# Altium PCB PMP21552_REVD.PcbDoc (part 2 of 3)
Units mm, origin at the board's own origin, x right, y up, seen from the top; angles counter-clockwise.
Board outline 45.05 x 86.02 mm, 4 copper layers (Top Layer, Signal Layer 1, Signal Layer 2, Bottom Layer), stack 1.006 mm thick; 146 components, 80 nets, 395 pads, 82 vias.
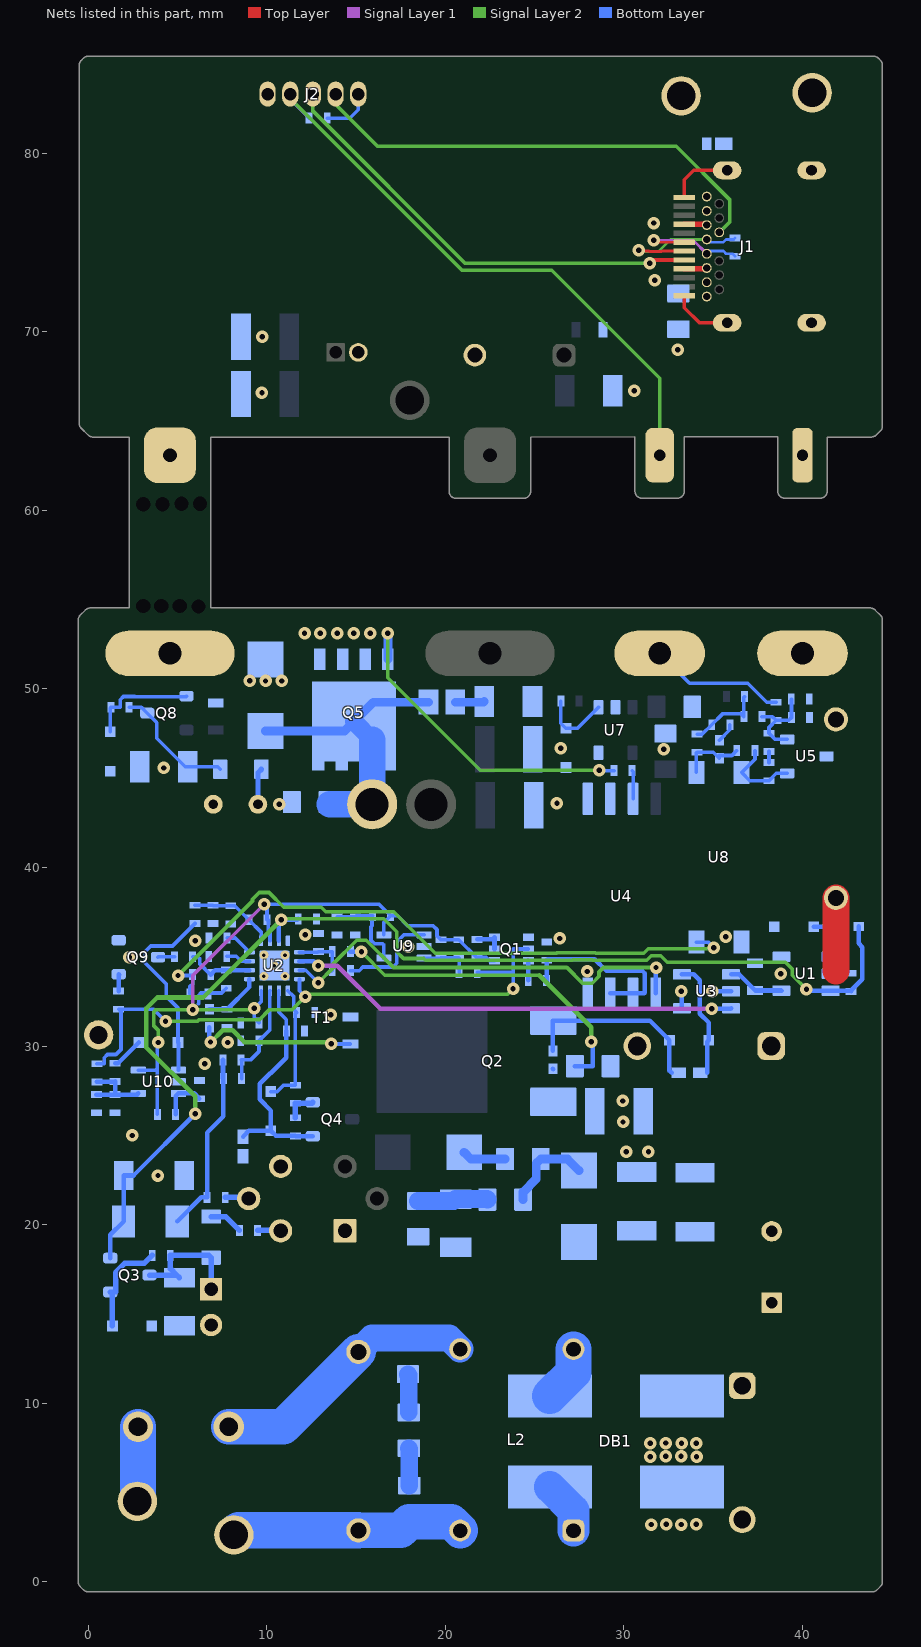
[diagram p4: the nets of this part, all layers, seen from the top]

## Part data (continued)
C33: library part CMP-0008251-2, "CAP, CERM, 1000 pF, 250 V, +/- 10%, X7R, 0805", Cap_Case=0805, Manufacturer=MuRata, Supplier Part Number 1=490-3525-1-ND, TempCo=X7R, Tolerance_%=10%, Value1=Unknown, Value2=250V, ValueDisplayed=1000pF
C34: library part CMP-0008252-2, "CAP, CERM, 1500 pF, 250 V, +/- 10%, X7R, 0805", Cap_Case=0805, Manufacturer=MuRata, Supplier Part Number 1=490-3527-1-ND, TempCo=X7R, Tolerance_%=10%, Value1=Unknown, Value2=250V, ValueDisplayed=1500pF
C36: library part CMP-0008995-2, "CAP, CERM, 0.22 uF, 50 V, +/- 10%, X7R, 1206", Cap_Case=1206, Manufacturer=MuRata, Supplier Part Number 1=GRM31MR71H224KA01L-ND, TempCo=X7R, Tolerance_%=10%, Value1=Unknown, Value2=50V, ValueDisplayed=0.22uF
C37: library part CMP-0081668-2, "CAP, Aluminum Polymer, 680 µF, 25 V,+/- 20%, 0.29256 ohm, TH", Cap_Case=10x12mm, Manufacturer="Illinois Capacitor", Supplier Part Number 1=1572-1754-ND, Tolerance_%=20%, Value1="0.29256 ohm", Value2=25V, ValueDisplayed=680µF
C43: library part CMP-0006674-2, "CAP, CERM, 0.01 uF, 50 V, +/- 10%, X7R, 0402", Cap_Case=0402, Manufacturer=MuRata, Supplier Part Number 1=490-4516-1-ND, TempCo=X7R, Tolerance_%=10%, Value1=Unknown, Value2=50V, ValueDisplayed=0.01uF
C44: library part CMP-0008487-2, "CAP, CERM, 0.1 uF, 100 V, +/- 5%, X7R, 1206", Cap_Case=1206, Manufacturer=AVX, Supplier Part Number 1=478-3785-1-ND, TempCo=X7R, Tolerance_%=5%, Value1="0.037 ohm", Value2=100V, ValueDisplayed=0.1uF
D1 D13: library part CMP-0005829-1, "Diode, Zener, 10 V, 200 mW, SOD-323", Manufacturer="Diodes Inc.", Power_W=200mW, Supplier Part Number 1=MMSZ5240BS-FDICT-ND, Value1=0.2W
D2: "Diode, Zener, 9.1 V, 200 mW, SOD-323", Manufacturer="Diodes Inc.", Power_W=0.2, Supplier Part Number 1=BZT52C9V1S-FDICT-ND, Value1=0.2W
D3: library part CMP-0029199-1, "Diode, Superfast Rectifier, 200 V, 1 A, 3.5x1.6mm", Manufacturer="Comchip Technology", Supplier Part Number 1=641-1438-1-ND, Value1=1A, Value2=0.95V
D4 D21: library part CMP-0077868-1, "Diode, Standard Recovery Rectifier, 800 V, .2 A, 2x1.4mm", Manufacturer=Rohm, Supplier Part Number 1=RFU02VSM8SCT-ND, Value1=.2A, Value2=2.2V
D5: library part CMP-0005833-2, "Diode, Zener, 15 V, 200 mW, SOD-323", Manufacturer="Diodes Inc.", Power_W=200mW, Supplier Part Number 1=MMSZ5245BS-FDICT-ND, Value1=0.2W
D6: library part CMP-0005822-3, "Diode, TVS, Bi, 18 V, SOD-323", Manufacturer=Bourns, Value1=350W
D7: library part CMP-0005884-3, "Diode, Zener, 22 V, 300 mW, SOD-523", Manufacturer="Diodes Inc.", Power_W=300mW, Supplier Part Number 1=BZT52C22T-7DICT-ND, Value1=0.3W
D8: library part CMP-0028829-1, "Diode, Schottky, 30 V, 2 A, 2-XFDFN", Manufacturer="ON Semiconductor", Supplier Part Number 1=NSR20F30NXT5GOSCT-ND, Value1=2A, Value2=0.48V
D10: library part CMP-0077082-1, "Diode, Standard Recovery Rectifier, 1000 V, 1 A, AEC-Q101, SMA", Manufacturer="ON Semiconductor", Supplier Part Number 1=MRA4007T3GOSCT-ND, Value1=1A, Value2=1.1V
D11: library part CMP-0084982-1, "Diode, TVS, Uni, 150 V, 243 Vc, 400 W, 1.6 A, SMA", Manufacturer=Littelfuse, Value1=243V
D12 D100: library part CMP-0029006-2, "Diode, Ultrafast, 100 V, 0.25 A, SOD-323", Manufacturer=Nexperia, Value1=0.25A, Value2=1.4V
D14: library part CMP-0005466-2, "Diode, TVS, Bi, 100 V, SMA", Manufacturer=Littelfuse, Power_W=3.3W, Supplier Part Number 1=SMAJ100CALFCT-ND
DB1: "Diode, P-N-Bridge, 600 V, 4 A, Z4-D", Manufacturer="Comchip Technology", Supplier Part Number 1=641-1502-1-ND, Value1=4A, Value2=0.95V
F1: library part CMP-0003561-2, "Fuse, 3.15 A, 250VAC/VDC, TH", Irating_A=3.15A, Manufacturer=Littelfuse, Supplier Part Number 1=F5504CT-ND
J1: library part CMP-0054818-1, "Connector, Receptacle, USB Type C, R/A", Color=Black, Current_A=3A, Manufacturer="Wurth Elektronik", Voltage_V=5V
J2: library part CMP-0054560-1, "Header, 50mil, 5x1, Gold, TH", Manufacturer="Sullins Connector Solutions", Supplier Part Number 1=S9014E-05-ND
J3: library part CMP-0054555-1, "Header, 50mil, 2x1, Gold, TH", Manufacturer="Sullins Connector Solutions", Supplier Part Number 1=S9014E-02-ND
L1: library part CMP-0087546-1, "WE-FI Leaded Toroidal Line Choke", Manufacturer=Wurth
L2: library part CMP-0086351-1, "Coupled inductor, 1.3 mH, 0.035 ohm, TH", Manufacturer="Renco Electronics", ValueDisplayed=1.3mH
LOGO1: library part IEC_HighVoltage, "IEC 61010-1 High Voltage Warning"
LOGO2: library part CMP-0074837-1, "IEC 61010-1 Hot Surface Warning"
Logo3: library part CMP-0074839-1
Logo4: library part CMP-0074769-1
Q1: library part CMP-0000173-4, "MOSFET, 2-CH, N/P-CH, 20 V, 0.7 A, SOT-363", Alternate Manufacturer=None, Manufacturer=Vishay-Siliconix, Value1=0.3, Value2="1.2 nC"
Q2: library part CMP-0079238-2, "MOSFET, N-CH, 600 V, 12 A, DPAK", Alternate Manufacturer=None, Manufacturer="Infineon Technologies", Supplier Part Number 1=IPD60R280P7SAUMA1CT-ND, Value1="? ohm", Value2="18 nC"
Q3 Q8: "MOSFET, N-CH, 100 V, 0.17 A, SOT-23", Alternate Manufacturer=None, Manufacturer="Fairchild Semiconductor", Supplier Part Number 1=BSS123NCT-ND, Value1="10 ohm", Value2="1.8 nC"
Q4: library part CMP-0067574-1, "MOSFET, N-CH, 600 V, 0.021 A, AEC-Q101, SOT-23", Alternate Manufacturer=None, Manufacturer="Infineon Technologies", Supplier Part Number 1=BSS126H6327XTSA2CT-ND, Value1="? ohm", Value2="1.4 nC"
Q5: library part CMP-0001046-2, "MOSFET, N-CH, 150 V, 87 A, PG-TDSON-8", Alternate Manufacturer=None, Manufacturer="Infineon Technologies", Supplier Part Number 1=BSC093N15NS5ATMA1CT-ND, Value2="33 nC"
Q9: library part CMP-0000281-1, "MOSFET, N-CH, 25 V, 0.22 A, SOT-23", Alternate Manufacturer=None, Manufacturer="Fairchild Semiconductor", Supplier Part Number 1=FDV301NCT-ND, Value2="0.49 nC"
R1: library part CMP-0026555-2, "RES, 7.50 k, 1%, 0.063 W, AEC-Q200 Grade 0, 0402", Manufacturer=Vishay-Dale, Power_W=63mW, Supplier Part Number 1=541-7.50KLCT-ND, TempCo="100 ppm/C", Tolerance_%=1%, Value2=0.063W, Value_Code=7k50, ValueDisplayed=7.50k
R2: library part CMP-0020554-3, "RES, 470 k, 5%, 0.125 W, AEC-Q200 Grade 0, 0805", Manufacturer=Vishay-Dale, Power_W=125mW, Supplier Part Number 1=541-470KACT-ND, TempCo="200 ppm/C", Tolerance_%=5%, Value2=0.125W, Value_Code=470k
R3 R32: library part CMP-0026027-3, "RES, 15.0 k, 1%, 0.063 W, AEC-Q200 Grade 0, 0402", Manufacturer=Vishay-Dale, Power_W=63mW, Supplier Part Number 1=541-15.0KLCT-ND, TempCo="100 ppm/C", Tolerance_%=1%, Value2=0.063W, Value_Code=15k0, ValueDisplayed=15.0k
R4: library part CMP-0026824-3, "RES, 100, 5%, 0.063 W, AEC-Q200 Grade 0, 0402", Manufacturer=Vishay-Dale, Power_W=63mW, Supplier Part Number 1=541-100JCT-ND, TempCo="200 ppm/C", Tolerance_%=5%, Value2=0.063W, Value_Code=100R, ValueDisplayed=100
R5 R7: library part CMP-0020464-3, "RES, 15, 5%, 0.125 W, AEC-Q200 Grade 0, 0805", Manufacturer=Vishay-Dale, Power_W=125mW, Supplier Part Number 1=541-15ACT-ND, TempCo="200 ppm/C", Tolerance_%=5%, Value2=0.125W, Value_Code=15R0, ValueDisplayed=15
R6 R12 R42 R46 R47: library part CMP-0026721-1, "RES, 100 k, 1%, 0.0625 W, 0402", Manufacturer="Yageo America", Power_W=62.5mW, Supplier Part Number 1=311-100KLRCT-ND, TempCo="100 ppm/C", Tolerance_%=1%, Value2=0.0625W, Value_Code=100k
R8 R14 R17: library part CMP-0026158-2, "RES, 200 k, 1%, 0.063 W, AEC-Q200 Grade 0, 0402", Manufacturer=Vishay-Dale, Power_W=63mW, Supplier Part Number 1=541-200KLCT-ND, TempCo="100 ppm/C", Tolerance_%=1%, Value2=0.063W, Value_Code=200k
R9: library part CMP-0026543-2, "RES, 75.0 k, 1%, 0.063 W, AEC-Q200 Grade 0, 0402", Manufacturer=Vishay-Dale, Power_W=63mW, Supplier Part Number 1=541-75.0KLCT-ND, TempCo="100 ppm/C", Tolerance_%=1%, Value2=0.063W, Value_Code=75k0, ValueDisplayed=75.0k
R10: library part CMP-0026208-2, "RES, 26.7 k, 1%, 0.063 W, AEC-Q200 Grade 0, 0402", Manufacturer=Vishay-Dale, Power_W=63mW, Supplier Part Number 1=541-26.7KLCT-ND, TempCo="100 ppm/C", Tolerance_%=1%, Value2=0.063W, Value_Code=26k7, ValueDisplayed=26.7k
R11: library part CMP-0026822-3, "RES, 0, 5%, 0.063 W, AEC-Q200 Grade 0, 0402", Manufacturer=Vishay-Dale, Power_W=63mW, Supplier Part Number 1=541-0.0JCT-ND, TempCo="200 ppm/C", Tolerance_%=5%, Value2=0.063W, Value_Code=0000, ValueDisplayed=0
R13: library part CMP-0026284-2, "RES, 30.1 k, 1%, 0.063 W, AEC-Q200 Grade 0, 0402", Manufacturer=Vishay-Dale, Power_W=63mW, Supplier Part Number 1=541-30.1KLCT-ND, TempCo="100 ppm/C", Tolerance_%=1%, Value2=0.063W, Value_Code=30k1, ValueDisplayed=30.1k
R15: library part CMP-0025951-3, "RES, 100, 1%, 0.063 W, AEC-Q200 Grade 0, 0402", Manufacturer=Vishay-Dale, Power_W=63mW, Supplier Part Number 1=541-100LCT-ND, TempCo="100 ppm/C", Tolerance_%=1%, Value2=0.063W, Value_Code=100R, ValueDisplayed=100
R16: library part CMP-0026825-5, "RES, 10 k, 5%, 0.063 W, AEC-Q200 Grade 0, 0402", Manufacturer=Vishay-Dale, Power_W=63mW, Supplier Part Number 1=541-10KJCT-ND, TempCo="200 ppm/C", Tolerance_%=5%, Value2=0.063W, Value_Code=10k0, ValueDisplayed=10k
R18 R38: library part CMP-0026436-2, "RES, 511, 1%, 0.063 W, AEC-Q200 Grade 0, 0402", Manufacturer=Vishay-Dale, Power_W=63mW, Supplier Part Number 1=541-511LCT-ND, TempCo="100 ppm/C", Tolerance_%=1%, Value2=0.063W, Value_Code=511R, ValueDisplayed=511
R19: library part CMP-0026542-2, "RES, 750, 1%, 0.063 W, AEC-Q200 Grade 0, 0402", Manufacturer=Vishay-Dale, Power_W=63mW, Supplier Part Number 1=541-750LCT-ND, TempCo="100 ppm/C", Tolerance_%=1%, Value2=0.063W, Value_Code=750R, ValueDisplayed=750
R20: library part CMP-0026453-2, "RES, 56.2 k, 1%, 0.063 W, AEC-Q200 Grade 0, 0402", Manufacturer=Vishay-Dale, Power_W=63mW, Supplier Part Number 1=541-56.2KLCT-ND, TempCo="100 ppm/C", Tolerance_%=1%, Value2=0.063W, Value_Code=56k2, ValueDisplayed=56.2k
R21: library part CMP-0015175-1, "RES, 0.22, 1%, 0.5 W, 1210", Manufacturer=Rohm, Power_W=500mW, Supplier Part Number 1=RHM.22SCT-ND, TempCo="200 ppm/C", Tolerance_%=1%, Value2=0.5W, Value_Code=R220, ValueDisplayed=0.22
R22 R24 R29 R34: library part CMP-0026859-2, "RES, 1.0 M, 5%, 0.063 W, AEC-Q200 Grade 0, 0402", Manufacturer=Vishay-Dale, Power_W=63mW, Supplier Part Number 1=541-1.0MJCT-ND, TempCo="200 ppm/C", Tolerance_%=5%, Value2=0.063W, Value_Code=1M00, ValueDisplayed=1.0M
R23: library part CMP-0026004-3, "RES, 13.3 k, 1%, 0.063 W, AEC-Q200 Grade 0, 0402", Manufacturer=Vishay-Dale, Power_W=63mW, Supplier Part Number 1=541-13.3KLCT-ND, TempCo="100 ppm/C", Tolerance_%=1%, Value2=0.063W, Value_Code=13k3, ValueDisplayed=13.3k
R25 R31: library part CMP-0026669-1, "RES, 150 k, 1%, 0.1 W, AEC-Q200 Grade 0, 0402", Manufacturer=Panasonic, Power_W=100mW, Supplier Part Number 1=P150KLCT-ND, TempCo="100 ppm/C", Tolerance_%=1%, Value2=0.1W, Value_Code=150k
R26: library part CMP-0026329-2, "RES, 3.01 k, 1%, 0.063 W, AEC-Q200 Grade 0, 0402", Manufacturer=Vishay-Dale, Power_W=63mW, Supplier Part Number 1=541-3.01KLCT-ND, TempCo="100 ppm/C", Tolerance_%=1%, Value2=0.063W, Value_Code=3k01, ValueDisplayed=3.01k
R27: library part CMP-0026505-2, "RES, 681, 1%, 0.063 W, AEC-Q200 Grade 0, 0402", Manufacturer=Vishay-Dale, Power_W=63mW, Supplier Part Number 1=541-681LCT-ND, TempCo="100 ppm/C", Tolerance_%=1%, Value2=0.063W, Value_Code=681R, ValueDisplayed=681
R28: library part CMP-0026196-2, "RES, 24.9 k, 1%, 0.063 W, AEC-Q200 Grade 0, 0402", Manufacturer=Vishay-Dale, Power_W=63mW, Supplier Part Number 1=541-24.9KLCT-ND, TempCo="100 ppm/C", Tolerance_%=1%, Value2=0.063W, Value_Code=24k9, ValueDisplayed=24.9k
R30: library part CMP-0026162-2, "RES, 20.0 k, 1%, 0.063 W, AEC-Q200 Grade 0, 0402", Manufacturer=Vishay-Dale, Power_W=63mW, Supplier Part Number 1=541-20.0KLCT-ND, TempCo="100 ppm/C", Tolerance_%=1%, Value2=0.063W, Value_Code=20k0, ValueDisplayed=20.0k
R33: library part CMP-0021883-2, "RES, 1.50, 1%, 0.125 W, 0805", Manufacturer="Yageo America", Power_W=125mW, Supplier Part Number 1=311-1.50CRCT-ND, TempCo="200 ppm/C", Tolerance_%=1%, Value2=0.125W, Value_Code=1R50, ValueDisplayed=1.50
R35: "RES, 100, 5%, 0.063 W, 0402", Manufacturer=Vishay-Dale, Power_W=0.063, Supplier Part Number 1=541-100JCT-ND, TempCo="200 ppm/C", Tolerance_%=5, Value1=5%, Value2=0.063W, Value_Code=100R, ValueDisplayed=100
R36 R39: library part CMP-0026393-2, "RES, 475 k, 1%, 0.063 W, AEC-Q200 Grade 0, 0402", Manufacturer=Vishay-Dale, Power_W=63mW, Supplier Part Number 1=541-475KLCT-ND, TempCo="100 ppm/C", Tolerance_%=1%, Value2=0.063W, Value_Code=475k
R37 R44: library part CMP-0027004-2, "RES, 0, 5%, 0.063 W, 0402", Manufacturer="Yageo America", Power_W=63mW, Supplier Part Number 1=311-0.0JRCT-ND, TempCo="200 ppm/C", Tolerance_%=5%, Value2=0.063W, Value_Code=0000, ValueDisplayed=0
R40: library part CMP-0025702-4, "RES, 10 M, 5%, 0.1 W, AEC-Q200 Grade 0, 0603", Manufacturer=Vishay-Dale, Power_W=100mW, Supplier Part Number 1=541-10MGCT-ND, TempCo="200 ppm/C", Tolerance_%=5%, Value2=0.1W, Value_Code=10M0, ValueDisplayed=10M
R41 R43 R54: library part CMP-0020574-3, "RES, 5.1 M, 5%, 0.125 W, AEC-Q200 Grade 0, 0805", Manufacturer=Vishay-Dale, Power_W=125mW, Supplier Part Number 1=541-5.1MACT-ND, TempCo="200 ppm/C", Tolerance_%=5%, Value2=0.125W, Value_Code=5M10, ValueDisplayed=5.1M
R45: library part CMP-0026280-2, "RES, 301 k, 1%, 0.063 W, AEC-Q200 Grade 0, 0402", Manufacturer=Vishay-Dale, Power_W=63mW, Supplier Part Number 1=541-301KLCT-ND, TempCo="100 ppm/C", Tolerance_%=1%, Value2=0.063W, Value_Code=301k
R48: library part CMP-0026325-2, "RES, 392 k, 1%, 0.063 W, AEC-Q200 Grade 0, 0402", Manufacturer=Vishay-Dale, Power_W=63mW, Supplier Part Number 1=541-392KLCT-ND, TempCo="100 ppm/C", Tolerance_%=1%, Value2=0.063W, Value_Code=392k
R49: library part CMP-0026205-2, "RES, 267 k, 1%, 0.063 W, AEC-Q200 Grade 0, 0402", Manufacturer=Vishay-Dale, Power_W=63mW, Supplier Part Number 1=541-267KLCT-ND, TempCo="100 ppm/C", Tolerance_%=1%, Value2=0.063W, Value_Code=267k
R50: library part CMP-0026605-2, "RES, 90.9 k, 1%, 0.063 W, AEC-Q200 Grade 0, 0402", Manufacturer=Vishay-Dale, Power_W=63mW, Supplier Part Number 1=541-90.9KLCT-ND, TempCo="100 ppm/C", Tolerance_%=1%, Value2=0.063W, Value_Code=90k9, ValueDisplayed=90.9k
R51: library part CMP-0026249-2, "RES, 2.21 M, 1%, 0.063 W, AEC-Q200 Grade 0, 0402", Manufacturer=Vishay-Dale, Power_W=63mW, Supplier Part Number 1=541-2.21MLCT-ND, TempCo="100 ppm/C", Tolerance_%=1%, Value2=0.063W, Value_Code=2M21, ValueDisplayed=2.21M
R52: library part CMP-0026866-3, "RES, 1.0, 5%, 0.063 W, AEC-Q200 Grade 0, 0402", Manufacturer=Vishay-Dale, Power_W=63mW, Supplier Part Number 1=541-1.0JCT-ND, TempCo="200 ppm/C", Tolerance_%=5%, Value2=0.063W, Value_Code=1R00, ValueDisplayed=1.0
R53: library part CMP-0018578-3, "RES, 10, 5%, 0.25 W, AEC-Q200 Grade 0, 1206", Manufacturer=Vishay-Dale, Power_W=250mW, Supplier Part Number 1=541-10ECT-ND, TempCo="200 ppm/C", Tolerance_%=5%, Value2=0.25W, Value_Code=10R0, ValueDisplayed=10
R55: "RES, 1.0 M, 5%, 0.063 W, 0402", Manufacturer=Vishay-Dale, Power_W=0.063, Supplier Part Number 1=541-1.0MJCT-ND, TempCo="200 ppm/C", Tolerance_%=5, Value1=5%, Value2=0.063W, Value_Code=1M00, ValueDisplayed=1.0M
R56: library part CMP-0026942-3, "RES, 4.7, 5%, 0.063 W, AEC-Q200 Grade 0, 0402", Manufacturer=Vishay-Dale, Power_W=63mW, Supplier Part Number 1=541-4.7JCT-ND, TempCo="200 ppm/C", Tolerance_%=5%, Value2=0.063W, Value_Code=4R70, ValueDisplayed=4.7
R200: library part CMP-0026490-2, "RES, 61.9 k, 1%, 0.063 W, AEC-Q200 Grade 0, 0402", Manufacturer=Vishay-Dale, Power_W=63mW, Supplier Part Number 1=541-61.9KLCT-ND, TempCo="100 ppm/C", Tolerance_%=1%, Value2=0.063W, Value_Code=61k9, ValueDisplayed=61.9k
RT1: library part CMP-0002523-3, "Thermistor NTC, 47k ohm, 5%, 0603", Manufacturer=MuRata, Power_W=100mW, Supplier Part Number 1=490-2428-1-ND, Tolerance_%=5%
T1: library part CMP-0087465-1, "MODIFIED RLTI-1324 TRANSFORMER", Manufacturer="Renco Electronics"
TP1 TP4: library part CMP-0055148-1, "Test Point, Multipurpose, Black, TH", Color=Black, Manufacturer=Keystone, PartNumber=5011, Supplier Part Number 1=36-5011-ND
TP2: library part CMP-0055149-1, "Test Point, Multipurpose, White, TH", Color=White, Manufacturer=Keystone, PartNumber=5012, Supplier Part Number 1=36-5012-ND
TP3 TP5: library part CMP-0055147-1, "Test Point, Multipurpose, Red, TH", Color=Red, Manufacturer=Keystone, Supplier Part Number 1=36-5010-ND
U1 U7: library part CMP-0066933-1, "50-mA 40-V Voltage-Tracking LDO With 5-mV Tracking Tolerance, DBV0005A (SOT-23-5)", Alternate Manufacturer="Texas Instruments"
U2: library part CMP-0860425-1, "High Frequency Active Clamp Flyback Controller, RTE0016C (WQFN-16)", Alternate Manufacturer="Texas Instruments"
U3: library part CMP-0066947-1, "4A/4A Single Channel High-speed Low-side Gate Driver, DBV0005A (SOT-23-5)", Alternate Manufacturer="Texas Instruments", Alternate PartNumber=UCC27517DBVT
U4: library part CMP-0860377-2, "4-A/6-A, Single-Channel Reinforced Isolation Gate Driver with High Noise Immunity, DWV0008A (SOIC-8)", Alternate Manufacturer="Texas Instruments"
U5: library part CMP-0066199-1, "2.5V Low Iq Adjustable Precision Shunt Regulator, DBZ0003A (SOT-23-3)", Alternate Manufacturer="Texas Instruments"
U8: library part CMP-0006160-3, "Optocoupler, 5 kV, 63-125% CTR, SMT", Manufacturer=Vishay-Semiconductor, Supplier Part Number 1=VOL618A-2TCT-ND, Voltage_Isolation_Vrms=5kV
U9 U10: library part CMP-0085889-2, "Small-Size Micropower Low-Voltage Comparator, DCK0005A (SOT-SC70-5)", Alternate Manufacturer="Texas Instruments", Alternate PartNumber=TLV7021DCKT, Operating Temperature Range="-40 to 125 C", Rating=Catalog

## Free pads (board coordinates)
  oval 7.239x2.54 hole 1.27 slot 5.08 at 0 deg: 0(4.572,52) 0(22.5,52)
  oval 5.08x2.54 hole 1.27 slot 3.048 at 0 deg: 0(32,52) 0(40,52)
  round 1.65 hole 1: 1(0.575,30.625)
  round 0 hole 0.8 unplated mask+0.075: 1(3.075,54.65) 1(3.075,60.35) 1(4.086,54.65) 1(4.15,60.35) 1(5.125,54.65) 1(5.224,60.375) 1(6.175,54.625) 1(6.25,60.375)
  rrect50% 2.9x3.1 hole 0.762: 2(4.572,63.096) 2(22.5,63.096)
  rrect50% 1.6x3.048 hole 0.635: 2(32,63.096)
  rrect50% 1.143x3.048 hole 0.635: 2(40,63.096)

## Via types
v1: diameter 0.7, hole 0.3, Top Layer to Bottom Layer, 77 vias
v2: diameter 0.5, hole 0.2, Top Layer to Bottom Layer, 5 vias

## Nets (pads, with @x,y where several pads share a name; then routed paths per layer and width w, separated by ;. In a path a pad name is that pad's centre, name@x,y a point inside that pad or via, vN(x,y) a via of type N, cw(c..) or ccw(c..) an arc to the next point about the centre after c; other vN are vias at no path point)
CC1: J1.A5 J2.3 | length 25.4
  Top Layer w0.203: v1(31.45,73.85) 31.63,74.03 J1.A5@33.38,74.03
  Signal Layer 2 w0.203: J2.3@12.58,83.325 12.58,82.37 21.1,73.85 v1(31.45,73.85)
CC2: J1.B5 J2.4 | length 26.9
  Signal Layer 2 w0.203: J2.4@13.85,83.325 13.85,82.75 16.2,80.4 32.935,80.4 35.917,77.419 35.917,76.141 35.355,75.58 J1.B5@35.34,75.58
CS: C21.2 R19.1 R38.2 U2.1 | length 2.9
  Bottom Layer w0.203: U2.1@11.825,35.25 12.858,35.25 C21.2@12.9,35.292 R19.1@13.667,35.292 R38.2@13.667,34.225
CTL: pad.0@32,52 R28.1 | length 7.7
  Bottom Layer w0.2: pad.0@32,52 33.675,50.325 36.928,50.325 37.995,49.258 R28.1@38.525,49.258
CTL2: J2.2 pad.2@32,63.096 R3.2 | length 33.5
  Signal Layer 2 w0.203: J2.2@11.31,83.325 11.31,83.07 20.933,73.447 25.953,73.447 32,67.4 pad.2@32,63.096
  Bottom Layer w0.203: J2.2@11.31,83.325 11.31,83.032 R3.2@12.367,81.975
DN: J1.A7 J1.B7 R35.1 | length 6.9
  Top Layer w0.152: v1(31.675,75.13) 31.775,75.03 J1.A7@33.38,75.03
  Signal Layer 1 w0.152: v1(31.675,75.13) 33.89,75.13 J1.B7@34.64,74.38
  Bottom Layer w0.152: J1.B7@34.64,74.38 34.64,74.531 35.568,74.531 35.72,74.38 36.087,74.38 R35.1@36.225,74.242
DP: J1.A6 J1.B6 R35.2 | length 8.6
  Top Layer w0.152: v1(30.825,74.575) 30.87,74.53 31.389,74.53 31.416,74.504 32.104,74.504 32.13,74.53 J1.A6@33.38,74.53
  Signal Layer 2 w0.152: v1(30.825,74.575) 30.896,74.504 31.934,74.504 32.611,75.18 J1.B6@34.64,75.18
  Bottom Layer w0.152: J1.B6@34.64,75.18 34.64,75.029 35.568,75.029 35.72,75.18 36.147,75.18 R35.2@36.225,75.258
DRV: U2.2 U3.3 | length 25.3
  Signal Layer 1 w0.254: v1(12.883,34.5) 13.95,34.5 16.35,32.1 v1(34.925,32.1)
  Bottom Layer w0.254: U2.2@11.825,34.75 12.633,34.75 v1(12.883,34.5) ; v1(34.925,32.1) 35.983,32.1 U3.3@36,32.117
ENSR: Q1.2 R36.1 R37.2 R45.1 U2.4 | length 33.5
  Signal Layer 2 w0.203: v1(4.325,31.392) 6.12,31.392 6.193,31.465 9.572,31.465 10.15,32.044 11.419,32.044 v1(12.15,32.775) 12.273,32.898 23.482,32.898 v1(23.79,33.206)
  Bottom Layer w0.203: R45.1@0.475,29.008 0.894,29.008 0.894,29.348 1.07,29.525 1.544,29.525 1.828,29.809 1.828,31.939 R37.2@1.7,32.067 3.65,32.067 v1(4.325,31.392) ; U2.4@11.825,33.75 11.825,33.1 v1(12.15,32.775) ; R36.1@21.783,34.125 23.74,34.125 23.79,34.075 ; v1(23.79,33.206) 23.79,34.075 ; Q1.2@24.65,35.434 23.804,35.434 23.79,35.42 23.79,34.075
FB: C14.1 R30.1 R39.2 U2.10 | length 3.9
  Bottom Layer w0.2: R39.2@5.843,35 6.128,35 6.25,34.877 6.25,34.61 6.252,34.608 6.252,34.596 6.847,34 R30.1@6.858,34
  Bottom Layer w0.254: R30.1@6.858,34 7.116,34.258 C14.1@7.725,34.258 7.733,34.25 U2.10@9.025,34.25
HVG: C23.1 D6.2 D7.1 Q4.1 R24.2 U2.6 | length 13.1
  Bottom Layer w0.2: U2.6@10.675,33.1 10.675,31.902 11.092,31.485 C23.1@11.092,30.85
  Bottom Layer w0.254: D7.1@8.667,24.925 8.992,25.25 D6.2@10.225,25.25 ; C23.1@11.092,30.85 11.092,29.342 10.225,28.475 10.188,28.475 9.598,27.885 9.598,27.015 10.225,26.388 D6.2@10.225,25.25 ; Q4.1@12.575,24.95 11.617,24.95 R24.2@11.6,24.967 10.508,24.967 D6.2@10.225,25.25
NetC1_1: C1.1 DB1.1 L1.1
NetC3_1: C3.1 F1.1 L2.4 R41.2 | length 15.3
  Bottom Layer w1.5: C3.1@15.125,12.875 15.891,13.641 17.9,13.641 20.209,13.641 L2.4@20.825,13.025
  Bottom Layer w2: F1.1@7.865,8.675 10.925,8.675 C3.1@15.125,12.875
NetC3_2: C3.2 L2.2 R54.1 TP2.1 | length 13.2
  Bottom Layer w2: C3.2@15.125,2.875 17.491,2.875 17.975,3.359 20.331,3.359 L2.2@20.825,2.865
  Bottom Layer w2.032: TP2.1@8.153,2.616 8.412,2.875 C3.2@15.125,2.875
NetC6_2: C6.2 R2.1 R5.2 | length 3.9
  Bottom Layer w1: R2.1@18.475,21.316 20.466,21.316 C6.2@20.575,21.425 22.325,21.425 R5.2@22.35,21.4
NetC10_2: C10.2 C18.1 D1.2 Q2.3 R16.1 R19.2 R21.2 R33.1 U1.2 U1.5 U3.2 U3.4 | length 20.5
  Signal Layer 2 w0.2: v1(15.3,35.274) 16.602,33.971 25.253,33.971
  Signal Layer 2 w0.254: 25.253,33.971 28.175,31.049 v1(28.175,30.25)
  Bottom Layer w0.254: R19.2@14.683,35.292 15.282,35.292 v1(15.3,35.274) ; R16.1@26.025,28.725 R16.1@26.05,28.7 ; R33.1@27.25,28.875 28.25,28.875 28.25,30.175 v1(28.175,30.25) ; v1(33.203,33.067) 33.25,33.02 U3.4@33.25,32.117 ; v1(34.95,33.067) U3.2@36,33.067
  other v1: 38.778,34.05
NetC11_1: C11.1 D21.1 Q8.3 R55.1 | length 7.1
  Bottom Layer w0.2: R55.1@2.283,48.975 2.975,48.975 Q8.3@3.3,48.65 3.83,48.12 3.83,47.245 5.425,45.65 C11.1@5.575,45.65 7.244,45.65 D21.1@7.392,45.502
NetC13_2: C13.2 R13.2 R14.1 R50.2 U2.13 | length 4.8
  Bottom Layer w0.2: R50.2@5.975,37.883 R13.2@6.975,37.883 7,37.858 C13.2@7.975,37.858 8.209,37.858 R14.1@8.992,37.075 9.675,36.392 U2.13@9.675,35.9
NetC16_1: C16.1 C44.1 D4.1 Q3.3 R17.1 | length 7.1
  Bottom Layer w0.305: Q3.3@3.425,17.175 C44.1@4.95,17.175 ; C44.1@5.1,17.025 C44.1@4.95,17.175 ; C16.1@6.875,16.375 D4.1@6.875,18.15 6.75,18.275 R17.1@4.591,18.275 4.591,17.534 C44.1@4.95,17.175
NetC18_2: C18.2 U1.4 U3.1 | length 3.2
  Bottom Layer w0.254: U3.1@36,34.017 36.446,34.017 C18.2@37.35,33.113 38.812,33.113 U1.4@38.825,33.1
NetC19_2: C19.2 R1.1 U2.9 | length 3.2
  Bottom Layer w0.254: R1.1@6.775,32.064 6.781,32.058 C19.2@7.774,32.058 9.025,33.309 U2.9@9.025,33.75
NetC20_2: C20.2 R20.1 R23.2 U2.7 | length 5.9
  Bottom Layer w0.203: C20.2@8.583,28.175 8.583,29.2 R20.1@8.558,29.225 9.083,29.225 9.558,29.7 R23.2@9.558,30.3 10.16,30.902 10.16,33.085 U2.7@10.175,33.1
NetC25_1: C25.1 R25.2 R26.2 R44.2 | length 4.3
  Bottom Layer w0.2: R26.2@34.1,47.476 34.394,47.476 C25.1@34.917,47.999 35.522,48.604 36.563,48.604 R25.2@36.717,48.45 36.717,49.534 R44.2@36.758,49.575
NetC25_2: C25.2 R27.2 | length 1.1
  Bottom Layer w0.2: R27.2@35.349,47.133 35.933,47.718 C25.2@35.933,47.999
NetC27_1: C27.1 R200.1 | length 0.6
  Bottom Layer w0.2: C27.1@38.125,45.881 R200.1@38.125,46.506
NetC27_2: C27.2 R32.1 U5.1 U8.2 | length 4.4
  Bottom Layer w0.2: R32.1@37.34,46.551 37.34,46.07 U8.2@36.595,45.325 37.055,44.865 C27.2@38.125,44.865 38.535,45.275 U5.1@39.142,45.275
NetC28_1: C28.1 R45.2 R46.1 R49.1 U10.4 | length 4.1
  Bottom Layer w0.254: C28.1@0.45,27.283 R46.1@1.5,27.283 ; R45.2@0.475,27.992 1.475,27.992 R49.1@1.5,28.017 R46.1@1.5,27.283 ; U10.4@2.8,27.35 2.733,27.283 R46.1@1.5,27.283
NetC30_1: C30.1 R22.1 R34.1 U9.4 | length 5
  Bottom Layer w0.203: R34.1@13.938,37.241 C30.1@14.95,37.241 15.009,37.3 R22.1@15.917,37.3 15.887,37.27 15.887,36.745 15.829,36.687 15.829,35.933 16.035,35.727 16.497,35.727 16.556,35.668 U9.4@16.556,34.928
NetC31_2: C31.2 R36.2 R51.1 U9.3 | length 2.8
  Bottom Layer w0.203: U9.3@18.806,34.928 19.736,34.928 C31.2@19.75,34.942 R51.1@20.75,34.944 20.767,34.923 R36.2@20.767,34.125
NetC33_1: C33.1 R53.2 | length 1.6
  Bottom Layer w0.5: C33.1@20.55,49.258 22.133,49.258 R53.2@22.175,49.3
NetC33_2: C33.2 C34.1 D14.2 Q5.5 Q5.6 Q5.7 Q5.8 Q5.9 T1.B | length 17.4
  Bottom Layer w0.5: D14.2@9.925,47.65 14.35,47.65 Q5.9@14.875,48.175 15.958,49.258 C33.2@19.05,49.258
  Bottom Layer w1: C34.1@13.4,43.675 C34.1@13.533,43.542 ; Q5.9@14.875,48.175 Q5.9@15.9,47.15
  Bottom Layer w1.5: C34.1@13.533,43.542 T1.B@15.9,43.542 Q5.9@15.9,47.15
NetC43_2: C43.2 R4.1 U4.2 U4.3 | length 10
  Bottom Layer w0.254: R4.1@25.661,33.677 25.675,33.691 C43.2@25.675,34.807 25.722,34.854 28.375,34.854 28.997,34.232 31.011,34.232 31.153,34.09 31.153,32.975 31.128,32.95 U4.2@30.51,32.95 U4.3@29.24,32.95
NetD1_1: D1.1 R6.1 U1.1 | length 3.2
  Bottom Layer w0.254: D1.1@40.625,36.675 41.6,36.675 ; U1.1@41.575,35 41.575,36.65 41.6,36.675 ; R6.1@42.15,36.7 42.125,36.675 41.6,36.675
NetD2_1: D2.1 Q8.1 R55.2 | length 6.1
  Bottom Layer w0.2: D2.1@1.225,47.6 1.225,48.933 R55.2@1.267,48.975 1.793,48.975 1.793,49.404 1.968,49.58 2.598,49.58 2.603,49.575 5.475,49.575 Q8.1@5.5,49.6
NetD4_2: D4.2 R11.2 | length 1.9
  Bottom Layer w0.305: D4.2@6.875,20.45 7.692,20.45 R11.2@8.467,19.675
NetD5_1: D5.1 Q3.1 R17.2 | length 5.8
  Bottom Layer w0.305: D5.1@1.35,14.325 1.35,16.1 Q3.1@1.225,16.225 1.525,16.225 1.525,17.314 2.038,17.827 3.127,17.827 R17.2@3.575,18.275
NetD10_1: D10.1 R7.1 | length 2.4
  Bottom Layer w0.5: D10.1@21.05,24.05 21.425,23.675 R7.1@23.34,23.675
NetD11_1: D11.1 R5.1 R7.2 | length 5.1
  Bottom Layer w0.5: R5.1@24.35,21.4 24.35,21.822 25.09,22.562 25.09,23.425 R7.2@25.34,23.675 26.833,23.675 D11.1@27.483,23.025
NetD12_1: D12.1 R50.1 U10.1 | length 10.9
  Bottom Layer w0.203: U10.1@5.05,28.65 5.05,30.175 D12.1@5.025,30.2 5.025,32.128 4.373,32.78 4.373,33.465 3.198,34.64 3.198,35.315 3.49,35.606 4.714,35.606 R50.1@5.975,36.867
NetD12_2: D12.2 R49.2 | length 1.8
  Bottom Layer w0.254: R49.2@1.5,29.033 1.658,29.033 D12.2@2.825,30.2
NetD13_1: D13.1 R42.2 U7.1 | length 3.9
  Bottom Layer w0.2: R42.2@26.467,49.317 26.467,48.083 D13.1@26.75,47.8 27.4,47.8 U7.1@28.575,48.975
NetD21_2: D21.2 T1.C | length 2
  Bottom Layer w0.3: T1.C@9.5,43.542 9.5,45.31 D21.2@9.692,45.502
NetD100_1: D100.1 R15.1 U3.5 | length 6.6
  Bottom Layer w0.254: U3.5@33.25,34.017 33.908,34.017 34.248,33.677 34.248,31.82 34.75,31.318 D100.1@34.75,30.325 34.675,30.25 34.675,28.5
NetD100_2: D100.2 Q2.1 R15.2 R16.2 | length 10.5
  Bottom Layer w0.254: R16.2@26.025,29.725 26.025,31.405 Q2.1@26.05,31.43 31.445,31.43 D100.2@32.55,30.325 32.55,28.625 R15.2@32.675,28.5
NetDB1_2: DB1.2 L2.3 | length 3.2
  Bottom Layer w2: DB1.2@25.85,10.405 27.175,11.73 L2.3@27.175,13.025
NetDB1_3: DB1.3 L2.1 | length 3
  Bottom Layer w1.778: DB1.3@25.85,5.305 27.175,3.98 L2.1@27.175,2.865
NetF1_2: F1.2 TP1.1 | length 4.2
  Bottom Layer w2: TP1.1@2.75,4.5 2.785,4.535 F1.2@2.785,8.675
NetQ1_3: Q1.3 R4.2 | length 1.1
  Bottom Layer w0.254: R4.2@24.645,33.677 24.645,34.779 Q1.3@24.65,34.784
NetQ1_5: Q1.5 Q1.6 R12.2 | length 1.7
  Bottom Layer w0.254: R12.2@21.775,35.974 22.64,35.974 Q1.6@22.75,36.084 Q1.5@22.75,35.434
NetQ4_2: Q4.2 R18.2 R24.1 | length 1.8
  Bottom Layer w0.305: R24.1@11.6,25.983 R18.2@11.6,26.792 12.517,26.792 Q4.2@12.575,26.85
NetQ5_4: Q5.4 R52.2 | length 18.8
  Signal Layer 2 w0.2: v1(16.78,53.125) 16.78,50.628 21.958,45.45 v1(28.625,45.45)
  Bottom Layer w0.2: v1(28.625,45.45) 28.65,45.425 R52.2@29.442,45.425
  Bottom Layer w0.5: Q5.4@16.78,51.675 v1(16.78,53.125)
NetQ9_1: Q9.1 R37.1 | length 1
  Bottom Layer w0.254: R37.1@1.7,33.083 Q9.1@1.7,34.027 Q9.1@1.742,33.985
NetQ9_3: Q9.3 R39.1 | length 0.9
  Bottom Layer w0.2: Q9.3@3.9,34.977 3.922,35 R39.1@4.827,35
NetR1_2: R1.2 RT1.1 | length 9.3
  Signal Layer 2 w0.254: v1(6.845,30.226) 6.869,30.226 7.52,30.877 8.08,30.877 8.731,30.226 13.499,30.226 v1(13.6,30.125)
  Bottom Layer w0.203: v1(13.6,30.125) 13.612,30.113 RT1.1@14.675,30.113
  Bottom Layer w0.254: R1.2@6.775,31.048 6.775,30.296 v1(6.845,30.226)
NetR8_2: R8.2 U2.11 | length 1.4
  Bottom Layer w0.203: R8.2@7.758,35.025 8.287,35.025 8.562,34.75 U2.11@9.025,34.75
NetR9_1: R9.1 U2.12 | length 1.6
  Bottom Layer w0.203: R9.1@7.774,36.05 8.225,36.05 U2.12@9.025,35.25
NetR10_1: R10.1 R25.1 R28.2 R31.1 R200.2 U5.2 | length 4.9
  Bottom Layer w0.2: R25.1@37.733,48.45 38.317,48.45 R28.2@38.525,48.242 ; U5.2@39.142,47.175 38.472,47.175 R200.2@38.125,47.522 38.125,47.842 R28.2@38.525,48.242 ; R10.1@39.367,49.431 39.384,49.414 R31.1@39.384,48.4 39.226,48.242 R28.2@38.525,48.242
NetR11_1: R11.1 T1.5 | length 1.3
  Bottom Layer w0.305: R11.1@9.483,19.675 10.75,19.675 T1.5@10.772,19.653
NetR26_1: R26.1 R27.1 R32.2 U8.1 | length 3.8
  Bottom Layer w0.2: U8.1@34.055,45.325 34.055,46.415 R26.1@34.1,46.46 35.006,46.46 35.349,46.117 35.349,46.275 36.049,46.275 R32.2@36.324,46.551
NetR29_1: R29.1 R30.2 U8.4 | length 36.6
  Signal Layer 2 w0.203: v1(5.025,33.95) 9.198,38.123 9.198,38.22 9.58,38.602 10.12,38.602 10.945,37.777 13.045,37.777 13.295,37.527 17.102,37.527 19.425,35.203 26.225,35.203 26.25,35.229 28.387,35.229 28.412,35.203 31.116,35.203 31.364,35.452 34.968,35.452 v1(35.025,35.508)
  Bottom Layer w0.203: v1(5.025,33.95) 5.792,33.95 R30.2@5.842,34 5.842,33.492 5.69,33.34 R29.1@5.69,32.925 ; U8.4@34.055,35.825 34.708,35.825 v1(35.025,35.508)
NetR38_1: R38.1 U9.1 | length 5.7
  Bottom Layer w0.203: R38.1@14.683,34.225 15.173,34.225 15.374,34.427 17.077,34.427 17.283,34.633 17.283,35.274 17.273,35.283 17.273,35.823 17.679,36.228 U9.1@18.806,36.228
NetR41_1: R41.1 R43.2 | length 2.1
  Bottom Layer w1: R41.1@17.9,11.609 17.95,11.559 R43.2@17.95,9.491
NetR43_1: R43.1 R54.2 | length 2.1
  Bottom Layer w1: R43.1@17.95,7.459 17.975,7.434 R54.2@17.975,5.391
NetR47_1: R47.1 R48.1 U10.3 | length 2.5
  Bottom Layer w0.254: R48.1@4.884,26.175 4.884,27.184 U10.3@5.05,27.35 5.925,27.35 R47.1@6.225,27.05
NetR56_2: R56.2 T1.6 | length 1.3
  Bottom Layer w0.3: R56.2@7.666,21.525 8.913,21.525 T1.6@8.981,21.457
PGND: C1.2 C2.2 C4.1 C5.1 C12.2 C13.1 C15.2 C16.2 C17.2 C19.1 C21.1 C22.2 C23.2 C24.1 C28.2 C30.2 C43.1 C44.2 D5.2 D7.2 DB1.4 pad.1@0.575,30.625 Q1.1 Q9.2 R8.1 R9.2 R13.1 R21.1 R23.1 R33.2 R34.2 R46.2 R47.2 RT1.2 T1.7 U2.16 U2.17@10.425,34.5 U4.4 U8.3 U9.2 U10.2 | length 4.1
  Top Layer w1.5: 41.875,34.21 C15.2@41.875,38.3
  other v1: 31.525,3.2 33.203,3.2 32.375,3.225 34.042,3.225 31.484,7 33.2,7.016 34.066,7 32.338,7.025 31.464,7.75 33.225,7.75 34.055,7.75 32.35,7.763 3.9,22.75 30.125,24.075 31.375,24.075 2.45,24.991 29.95,25.75 29.925,26.925 6.527,29.008 7.8,30.2 13.578,31.75 27.951,34.177 2.3,34.977 17.925,35.553 5.982,35.9 26.4,36.025 35.699,36.125 12.15,36.225
  other v2: 9.835,33.91 11.015,33.91 10.425,34.5 9.835,35.09 11.015,35.09
REF: C12.1 C14.2 C31.1 Q1.4 R12.1 R14.2 R22.2 R29.2 R48.2 R51.2 U2.8 U2.14 U9.5 U10.5 | length 42.4
  Signal Layer 1 w0.203: v1(5.85,32.044) 5.85,33.95 v1(9.85,37.95)
  Signal Layer 2 w0.203: v1(3.925,30.2) 3.925,30.871 3.673,31.122 3.673,31.93 3.787,32.044 v1(5.85,32.044) 9.229,32.044 v1(9.302,32.117)
  Bottom Layer w0.203: U10.5@2.8,28.65 3.756,28.65 3.868,28.762 ; R48.2@3.868,26.175 3.868,28.762 ; v1(3.925,30.2) 3.868,30.143 3.868,28.762 ; 6.169,32.362 6.182,32.376 6.182,32.851 6.306,32.975 7.458,32.975 C14.2@7.725,33.242 ; C12.1@9.558,31.3 9.302,31.556 v1(9.302,32.117) 9.675,32.49 U2.8@9.675,33.1 ; U2.14@10.175,35.9 10.175,36.379 10.077,36.477 10.077,37.075 R14.2@10.008,37.075 10.008,37.792 v1(9.85,37.95) 16.283,37.95 R22.2@16.933,37.3 ; U9.5@16.556,36.228 16.556,36.923 R22.2@16.933,37.3 ; Q1.4@22.75,34.784 22.463,34.784 22.29,34.958 R12.1@21.775,34.958 21.752,34.958 R51.2@20.75,35.96 R51.2@20.75,35.96 C31.1@19.75,35.958 19.533,36.175 19.533,36.524 19.327,36.73 17.898,36.73 17.328,37.3 R22.2@16.933,37.3
SGND: C7.2 C8.2 C9.2 C11.2 C15.1 C26.2 C29.1 C34.2 D2.2 D13.2 D14.1 pad.0@4.572,52 pad.0@40,52 Q5.1 Q5.2 Q5.3 R10.2 R31.2 R53.1 T1.D U4.5 U4.6 U5.3 U7.2 U7.5
  other v1: 10.7,43.542 26.25,43.6 4.225,45.575 32.225,46.618 26.467,46.675 9.925,50.45 10.844,50.45 9.05,50.469 12.108,53.125 13,53.125 13.95,53.125 14.875,53.125 15.8,53.125
SGND2: C32.2 C36.2 C37.2 C39.2 C40.2 D8.2 J1.A1 J1.A12 J1.B1 J1.B12 J1.M1 J1.M2 J1.S1 J1.S2 J1.S3 J1.S4 J2.5 J3.2 pad.2@4.572,63.096 pad.2@40,63.096 R3.1 R40.1 TP4.1 | length 9.8
  Top Layer w0.203: J1.A1@33.38,72.03 33.38,71.359 34.229,70.51 J1.S1@35.78,70.51 ; J1.A12@33.38,77.53 33.38,78.52 33.91,79.05 J1.S4@35.78,79.05
  Bottom Layer w0.203: R3.1@13.383,81.975 14.65,81.975 15.12,82.445 J2.5@15.12,83.325
  other v1: 9.725,66.6 30.575,66.7 33.011,69 9.75,69.725
SR_drv: R52.1 U4.7 | length 1.6
  Bottom Layer w0.2: R52.1@30.458,45.425 30.51,45.373 U4.7@30.51,43.85
SRDRV: U2.3 U4.1 | length 24.3
  Signal Layer 2 w0.203: v1(12.883,33.55) 13.733,34.4 13.733,34.628 15.03,35.925 15.57,35.925 17.095,34.4 26.806,34.4 27.681,33.525 28.221,33.525 28.603,33.907 28.603,34.153 28.85,34.4 v1(31.8,34.4)
  Bottom Layer w0.203: U2.3@11.825,34.25 12.183,34.25 v1(12.883,33.55)
  Bottom Layer w0.254: U4.1@31.78,32.95 31.78,34.38 v1(31.8,34.4)
SWS: C24.2 D6.1 R18.1 U2.5 | length 7
  Bottom Layer w0.203: D6.1@10.225,27.45 10.575,27.45 10.933,27.808 R18.1@11.6,27.808 11.6,31.808 C24.2@11.667,31.875 11.498,32.044 11.498,32.777 U2.5@11.175,33.1
Vaux: C20.1 D3.2 R20.2 R56.1 | length 10.3
  Bottom Layer w0.254: D3.2@4.975,20.175 6.325,21.525 R56.1@6.65,21.525 6.65,25.15 7.567,26.067 C20.1@7.567,28.175 7.542,28.2 R20.2@7.542,29.225
Vbulk: C2.1 C4.2 C5.2 C6.1 D11.2 L1.2 R2.2 T1.1
VBUS: C32.1 D8.1 J1.A4 J1.A9 J1.B4 J1.B9 J2.1 TP3.1 | length 2.6
  Top Layer w0.3: J1.A4@33.38,73.53 34.64,73.53 J1.B9@34.64,73.58 ; J1.A9@33.38,76.03 34.59,76.03 J1.B4@34.64,75.98
  other v1: 31.725,72.9 31.675,76.1
Vdd_pri: C10.1 C17.1 C22.1 D3.1 Q3.2 R6.2 U1.3 U2.15 | length 67.9
  Signal Layer 2 w0.2: v1(10.8,37.075) 10.85,37.125 16.553,37.125 17.275,36.403 17.275,35.284 17.656,34.903 18.775,34.903 18.877,34.802 27.1,34.802 27.125,34.827 28.22,34.827 28.246,34.802 31.282,34.802 31.531,35.05 32.069,35.05 32.419,34.7 39.047,34.7 39.428,34.319 39.428,33.972 v1(40.225,33.175)
  Signal Layer 2 w0.254: v1(5.982,26.2) 5.982,27.185 3.248,29.92 3.248,30.941 3.245,30.945 3.245,32.108 3.858,32.721 6.446,32.721 v1(10.8,37.075)
  Bottom Layer w0.254: Q3.2@1.225,18.125 1.225,19.425 D3.1@1.975,20.175 C22.1@1.975,22.75 2.532,22.75 v1(5.982,26.2) ; U2.15@10.675,35.9 10.675,37.008 v1@10.742,37.075 ; v1(10.8,37.075) 11.709,37.075 C17.1@11.759,37.125 ; v1(40.225,33.175) 40.3,33.1 U1.3@41.575,33.1 42.684,33.1 C10.1@42.725,33.059 42.725,33.117 43.357,33.749 43.357,35.543 43.15,35.75 R6.2@43.15,36.7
